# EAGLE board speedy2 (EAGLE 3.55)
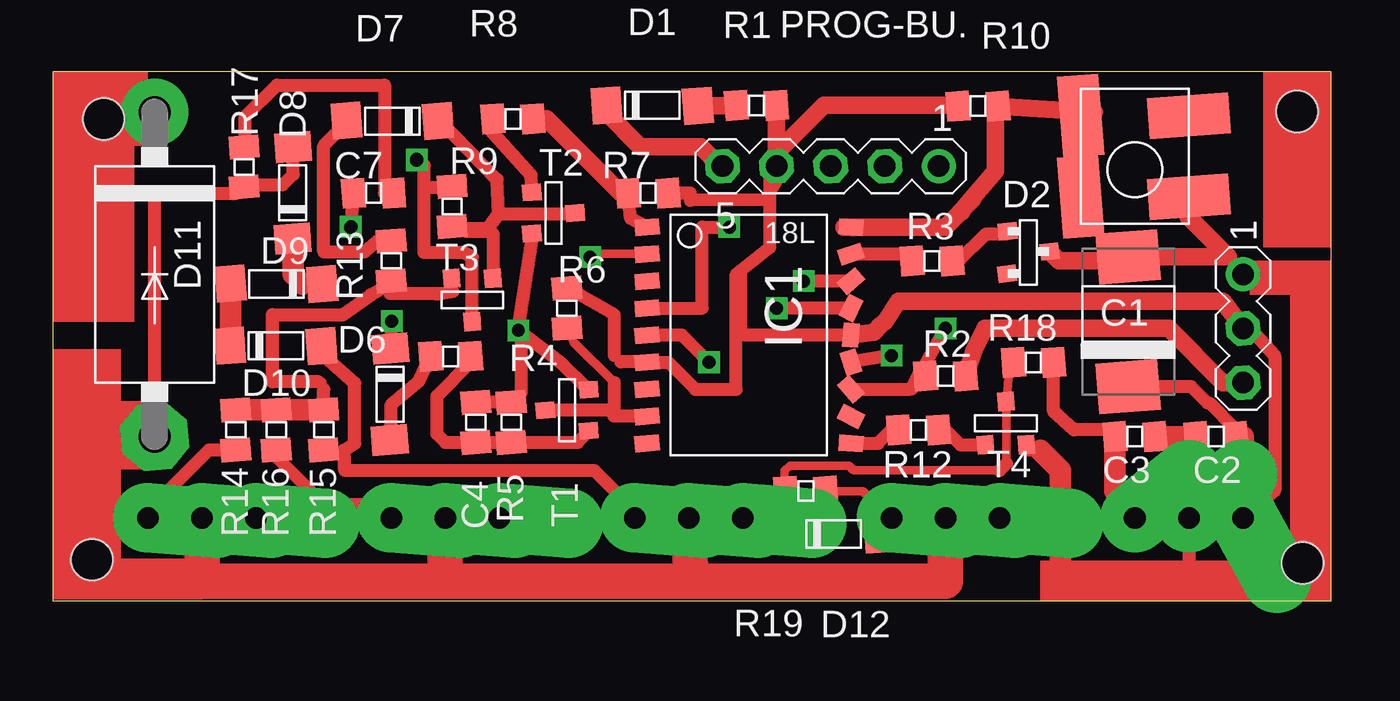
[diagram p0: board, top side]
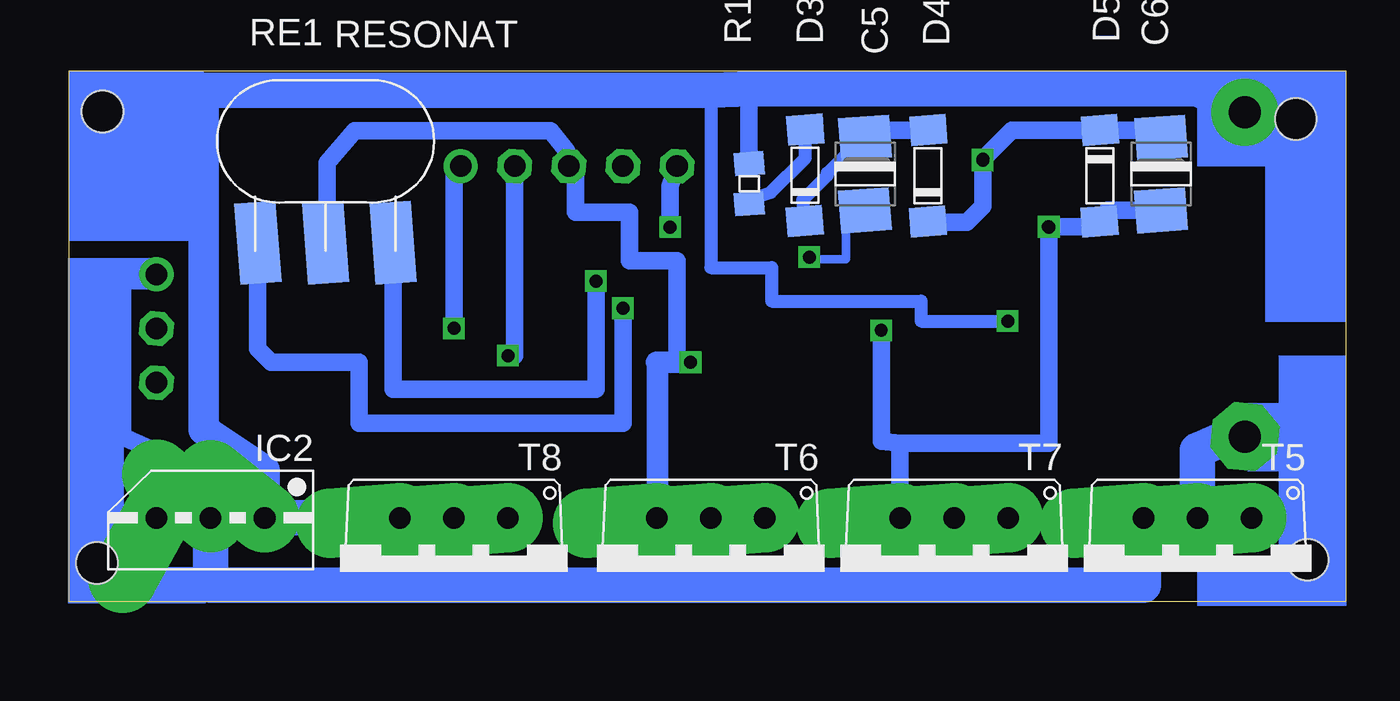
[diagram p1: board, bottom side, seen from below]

Size 60.01 x 24.88 mm. Coordinates in mm from the lower left corner, seen from the top.
Outline: 0,24.88 60.01,24.88 60.01,0 0,0 0,24.88
Copper layers used: Top, Bottom
Holes 1.93 mm at 2.37,22.66 1.82,1.96 58.67,1.81 58.42,23.01

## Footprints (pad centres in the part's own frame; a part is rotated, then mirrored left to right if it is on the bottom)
43 = smd 2.388 x 2.896 rotated 4.4:  3.048,0 | smd 2.388 x 2.896 rotated 4.3:  -3.048,0
05 = smd 1.092 x 1.397 rotated 4.4:  0.94,0 | smd 1.092 x 1.397 rotated 4.3:  -0.94,0
28 = smd 2.007 x 2.388 rotated 4.4:  1.702,0 | smd 2.007 x 2.388 rotated 4.3:  -1.702,0
D-80 = smd 1.397 x 1.702 rotated 4.4:  -2.388,0 | smd 1.397 x 1.702 rotated 4.3:  1.905,-0.025
T-23 = smd 0.787 x 0.889 rotated 6.7:  -1.24,-0.669 | smd 0.787 x 0.889 rotated 5.7:  0.754,-0.688 | smd 0.787 x 0.889 rotated 6.6:  -0.197,-2.662
201-15 = drill 1.499 pad 3.15 round:  -7.62,0 | drill 1.499 pad 3.15 octagon:  7.62,0
03-1 = drill 1.016 pad 1.6 round:  -2.54,0 | drill 1.016 pad 1.6 octagon:  0,0;  2.54,0
-18L = smd 0.762 x 1.143 rotated 4.3:  -5.08,-5.131;  5.08,4.445 | smd 0.762 x 1.143 rotated 4.4:  -3.81,-5.131 | smd 0.762 x 1.143 rotated 4.5:  -2.54,-5.131 | smd 0.762 x 1.143 rotated 4.6:  -1.27,-5.131 | smd 0.762 x 1.143 rotated 4.7:  0,-5.131;  1.27,-5.131 | smd 0.762 x 1.143 rotated 4.8:  2.54,-5.131 | smd 0.762 x 1.143 rotated 4.9:  3.81,-5.131 | smd 0.762 x 1.143 rotated 5:  5.08,-5.131 | smd 0.762 x 1.143 rotated 26.8:  3.81,4.445 | smd 0.762 x 1.143 rotated 49.3:  2.54,4.445 | smd 0.762 x 1.143 rotated 71.8:  1.27,4.445 | smd 0.762 x 1.143 rotated 94.3:  0,4.445 | smd 0.762 x 1.143 rotated 116.8:  -1.27,4.445 | smd 0.762 x 1.143 rotated 139.3:  -2.54,4.445 | smd 0.762 x 1.143 rotated 161.8:  -3.81,4.445 | smd 0.762 x 1.143 rotated 184.3:  -5.08,4.445
MXXS = drill 1.016 pad 3.251 offset:  -2.54,-2.54;  0,-2.54;  2.54,-2.54
05-1 = drill 1.016 pad 1.6 round:  -5.08,0 | drill 1.016 pad 1.6 octagon:  -2.54,0;  0,0;  2.54,0;  5.08,0
SONAT = smd 1.93 x 3.81 rotated 4.5:  3.175,-4.445 | smd 1.93 x 3.81 rotated 4.3:  -3.175,-4.445 | smd 1.93 x 3.81 rotated 4.4:  0,-4.445
T-23' = smd 0.787 x 0.889 rotated 4.4:  0.991,1.016 | smd 0.787 x 0.889 rotated 4.3:  -0.94,1.016 | smd 0.787 x 0.889 rotated 4.5:  0.025,-1.016
220V = drill 1.016 pad 3.251 offset:  -2.54,-2.54;  0,-2.54;  2.54,-2.54
D-SWIT = smd 3.81 x 1.93 rotated 4.3:  -2.54,1.27 | smd 3.81 x 1.93 rotated 4.4:  -2.54,-2.54 | smd 3.81 x 1.93 rotated 274.3:  2.54,1.27 | smd 3.81 x 1.93 rotated 274.4:  2.54,-2.54

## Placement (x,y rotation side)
C1  47u/10  [43]  50.48,13.13 90 top
C2  100n  [05]  54.61,7.74 0 top
C3  100n  [05]  50.8,7.74 180 top
C4  47n  [05]  19.85,8.41 90 top
C5  3u3/20  [28]  22.6,20.07 270 bottom
C6  3u3/20  [28]  8.7,20.07 270 bottom
C7  22n  [05]  15.04,19.17 0 top
D1  Smd-Standard  [D-80]  28.37,23.29 0 top
D2  LED-SMD  [T-23]  44.13,16.63 90 top
D3  LL4148  [D-80]  25.43,20.25 90 bottom
D4  LL4148  [D-80]  19.65,20.23 90 bottom
D5  ZDIO-18V  [D-80]  11.57,19.75 270 bottom
D6  ZDIO-5V1  [D-80]  15.83,9.49 270 top
D7  LL4148  [D-80]  15.68,22.55 180 top
D8  LL4148  [D-80]  11.24,19.43 90 top
D9  ZDIO-22V  [D-80]  10.25,14.91 180 top
D10  ZDIO-22V  [D-80]  10.7,12.02 0 top
D11  SB550  [201-15]  4.76,15.36 270 top
D12  LL4148  [D-80]  36.9,3.17 0 top
EMPF  MA03-1  [03-1]  55.88,12.82 270 top
IC1  16F84SO  [-18L]  33.02,12.5 270 top
IC2  LM2940CT  [MXXS]  53.34,1.39 180 bottom
PROG-BU.  MA05-1  [05-1]  36.51,20.44 180 top
R1  1k  [05]  33.02,23.3 180 top
R2  1k  [05]  41.91,10.59 180 top
R3  470  [05]  41.27,15.99 180 top
R4  1k  [05]  18.67,11.51 180 top
R5  2k2  [05]  21.5,8.41 270 top
R6  47k  [05]  24.13,13.77 90 top
R7  1k  [05]  27.94,19.17 0 top
R8  4k7  [05]  21.59,22.66 0 top
R9  47k  [05]  18.73,18.55 90 top
R10  1k  [05]  43.43,23.26 0 top
R11  47  [05]  28.04,19.62 90 bottom
R12  47k  [05]  40.64,8.05 0 top
R13  470  [05]  15.88,15.99 270 top
R14  220  [05]  8.57,8.05 90 top
R15  220  [05]  12.7,8.05 90 top
R16  220  [05]  10.48,8.05 90 top
R17  47  [05]  8.97,20.4 270 top
R18  10k  [05]  46.04,11.23 0 top
R19  82k  [05]  35.35,5.18 0 top
RE1  RESONAT  [SONAT]  47.94,21.29 0 bottom
T1  BC817  [T-23']  24.13,9.01 270 top
T2  BC817  [T-23']  23.49,18.21 90 top
T3  BC817  [T-23']  19.65,14.15 0 top
T4  BC817  [T-23']  44.77,8.37 180 top
T5  IRF3205  [220V]  6.98,1.39 180 bottom
T6  IRF3205  [220V]  29.84,1.39 180 bottom
T7  IRF3205  [220V]  18.41,1.39 180 bottom
T8  IRF9540 o..  [220V]  41.91,1.39 180 bottom
U$1  SMD-SWIT  [D-SWIT]  50.79,20.27 180 top

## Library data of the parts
C1 C5 C6 D1 D3-D10 D12 R11 R14 R19 = SMD
C2-C4 C7 R2 R15-R17 = DEMO
D2 RE1 U$1 = hans
D11 = DIODE
EMPF PROG-BU. = CON-LSTB
IC1 = PIC
IC2 = V-REG
R1 R3-R10 R12 R13 R18 = DISCRETE
T1-T4 = NPN
T5-T8 = FET

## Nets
+12V: C3. D6. D11. IC2. R11. R18. T8.
GND: C1. C2. C3. C4. C6. C7. D2. D5. EMPF. IC1. IC2. PROG-BU.. R5. RE1. T1. T2. T4. T5. T6. T7. U$1.
N$1: IC1. RE1.
N$3: IC1. PROG-BU..
N$4: C5. IC1.
N$5: D12. R19. T8.
N$6: IC1. R3.
N$8: D6. R4.
N$9: D2. R3.
N$10: R8. T2.
N$11: C4. R4. R5. T1.
N$12: IC1. R6. T1.
N$13: IC1. R7. R8.
N$14: R13. R14. R15. R16. T3.
N$15: R12. T4.
N$16: IC1. R12.
N$17: D12. R18. R19. T4.
N$18: D7. R9. T2. T3.
N$19: IC1. R10. U$1.
N$20: D8. D11. R17. T5. T6. T7. T8.
N$21: D7. R13.
N$22: IC1. RE1.
N$23: EMPF. R2.
N$24: D10. R15. T6.
N$26: D1. IC1. PROG-BU..
N$28: D8. D9.
N$29: IC1. PROG-BU.. R2.
N$30: C5. D3. D4.
N$32: R16. T7.
N$33: D3. R11.
N$34: D1. R1.
N$35: D9. D10.
N$36: C6. D4. D5. R9. T3.
N$37: C7. R17.
N$38: R14. T5.
VCC: C1. C2. EMPF. IC1. IC2. PROG-BU.. R1. R6. R7. R10.

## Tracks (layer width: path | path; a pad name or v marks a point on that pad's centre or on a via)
+12V  (via drill 0.61 pad 1.02)
  Top 0.406: 49.86,7.74 49.85,7.74 | 49.85,7.74 49.85,8.06 | 50.8,3.93 51.12,3.93 | 49.85,7.74 49.53,8.06
  Top 0.61: 51.12,3.93 49.86,5.18 | 46.98,11.23 46.97,8.93 47.94,8.06 49.53,8.06 | v15.9,13.17 15.87,13.17 15.87,11.88 15.83,11.88
  Top 1.016: 49.86,5.18 49.86,7.74
  Bottom 0.406: 50.8,6.15 50.8,6.47 | 50.8,3.93 50.8,3.61 | 27.94,24.06 28.02,24.06 28.04,24.04
  Bottom 0.61: v15.9,13.17 19.97,13.17 19.97,14.1 26.99,14.1 26.99,15.67 29.84,15.67 29.84,24.01
  Bottom 0.813: 28.04,24.04 28.04,20.56
  Bottom 1.422: 53.66,24.01 53.66,8.06 50.8,6.15 50.8,3.93
  Bottom 1.676: 4.76,22.98 6.98,24.06 27.94,24.06 29.84,24.01 53.66,24.01 56.83,23.98 | 50.8,3.93 T8.
GND  (via drill 0.61 pad 1.02)
  Top 0.406: 55.88,15.36 55.56,15.67 55.7,15.67 | v13.97,17.58 v13.98,17.59 | 25.15,9.95 25.09,9.95 25.08,9.96 24.77,10.28 | 22.54,17.26 22.53,17.28 22.48,17.28 | 50.48,16.18 50.48,15.99 50.16,16.31 | 45.72,7.1 45.71,7.12 45.71,7.36 | 27.81,12.53 27.84,12.53 27.87,12.56 27.93,12.5 | 53.34,7.74 53.44,7.74 53.47,7.71 53.5,7.74 C2. | 21.97,9.76 21.52,9.31 | 21.52,9.31 21.42,9.21 21.52,9.21 21.52,9.31 | 19.85,9.35 19.85,9.44 19.87,9.46 19.98,9.35 | v21.84,12.73 21.95,12.73 21.97,12.71 | 21.52,9.31 21.52,9.35 R5. | 55.7,15.67 55.92,15.46 | 55.7,15.67 55.19,16.18 | D2. 46.82,16.46 46.82,16.41
  Top 0.61: 47.31,1.07 53.02,1.07 53.34,1.39 53.34,3.93 | v30.8,11.23 29.53,12.5 27.93,12.5 | v13.98,17.59 C7. | 46.36,7.1 45.72,7.1 | 25.08,9.96 23.81,11.23 v21.84,12.73 22.54,17.26 | 21.97,12.71 21.97,9.76 | R5. 19.98,9.35
  Top 0.813: 50.48,16.18 55.19,16.18 53.29,18.09 53.29,18.96 53.33,19 | 50.48,15.99 47.23,15.99 46.82,16.41
  Top 1.016: 53.34,3.93 53.34,7.74 C3. | 47.31,1.07 47.31,6.15 46.36,7.1
  Bottom 0.406: T7. 20.95,2.34 20.64,0.75 20.95,1.07 | 32.38,3.61 T6. | 53.02,4.24 53.34,3.93 53.66,3.93 53.66,4.56 | 32.38,5.2 32.07,5.2 | 55.56,15.19 55.88,15.36 | 36.51,20.44 36.51,20.12 36.2,20.12 | v30.8,11.23 31.43,11.23 | v13.98,17.59 v13.97,17.58 13.96,17.57 | 11.83,17.59 11.59,17.83 D5. 11.61,17.84 11.67,17.91 11.21,18.37 | 36.62,20.36 36.62,21.16 | 47.87,16.36 47.97,16.26 47.97,16.16
  Bottom 0.813: v13.97,17.58 13.97,7.42 20.95,7.42 | T7. 20.95,7.42 | 53.66,4.56 54.61,6.47 57.47,7.74 57.47,15.14 55.56,15.19 | v21.84,12.73 21.84,7.52 20.95,7.42 | 36.2,20.12 36.2,18.28 33.66,18.28 33.66,15.99 31.43,15.99 31.43,11.23 | v13.98,17.59 11.83,17.59 | 36.62,21.16 37.37,22.11 46.57,22.11 47.87,20.61 47.87,16.36 | 11.21,18.37 8.7,18.37
  Bottom 1.016: 32.35,11.23 v30.8,11.23 | 32.35,11.23 32.38,11.23 | 32.35,11.23 32.35,3.8 32.36,3.8 | T6. 32.38,3.9 32.36,3.9 32.36,3.8 | T6. | 32.38,5.2 T6. | 32.36,3.8 32.36,3.77 | 36.45,20.44 36.45,20.5 | 36.51,20.44 36.45,20.44 | 36.62,20.36 36.45,20.36 36.45,20.44 | 47.87,16.36 47.94,16.36 RE1.
  Bottom 1.676: 32.38,0.75 20.64,0.75 9.52,0.75 T5. | 32.38,0.75 32.38,3.61 | 32.38,0.75 53.34,0.75 53.34,3.93 | 20.95,1.07 T7.
N$1  (via drill 0.61 pad 1.02)
  Top 0.406: v33.97,13.77 34,13.8
  Top 0.61: 34,13.8 37.39,13.8
  Bottom 0.61: 51.22,16.84 51.11,16.84 51.12,16.84 | 51.22,11.87 51.12,11.87
  Bottom 0.813: v33.97,13.77 33.97,8.37 46.36,8.37 46.36,11.23 50.48,11.23 51.12,11.87 | 51.12,11.87 51.12,16.84
N$3  (via drill 0.61 pad 1.02)
  Top 0.406: 39.39,11.57 v39.37,11.55
  Top 0.61: 37.39,11.26 39.39,11.57
  Bottom 0.406: v39.37,11.55 39.05,11.55
  Bottom 0.813: 39.05,11.55 39.05,20.44
N$4  (via drill 0.61 pad 1.02)
  Top 0.406: 27.81,16.34 27.8,16.32 25.37,16.32 v25.22,16.17
  Bottom 0.406: 22.6,18.37 23.49,18.37 23.49,16.08 25.22,16.08 v25.22,16.17
N$5
  Top 0.406: 39.29,3.91 39.31,3.93 39.37,3.93 | 36.29,5.18 38.02,5.18 39.29,3.91 | 38.77,3.14 38.77,3.12 | 38.77,3.14 D12. | 39.29,3.91 38.77,3.91 38.77,3.14
N$6
  Top 0.406: 40.34,15.99 40.32,15.99 40.32,16.34
  Top 0.61: 37.39,16.34 40.32,16.34
N$8
  Top 0.61: 17.73,11.51 17.17,10.36 15.87,9.26 15.87,7.61 15.84,7.58 D6.
N$9
  Top 0.406: R3. 42.55,15.99 | 44.77,17.26 44.82,17.32 44.82,17.38
  Top 0.61: 42.55,15.99 43.81,17.26 44.77,17.26
N$10
  Top 0.406: 20.5,22.16 R8.
  Top 0.61: 22.48,19.21 22.45,20 20.5,22.16
N$11
  Top 0.406: 25.12,8.02 25.15,8.02 | 25.12,8.02 25.07,8.07 | 21.5,7.47 21.51,7.47 21.57,7.41 | 25.17,8.01 25.16,8.02 25.12,8.02 | 19.61,11.25 R4. | C4. 19.85,7.44 19.82,7.41 19.77,7.46
  Top 0.61: C4. 21.5,7.47 24.63,7.47 25.17,8.01 | 19.61,11.25 18.02,9.66 18.02,7.86 18.42,7.46 19.77,7.46
N$12
  Top 0.406: 26.33,8.72 26.03,9.01 23.18,9.01 23.15,8.98 T1. | R6. 24.45,12.18 26.35,10.28
  Top 0.61: 26.33,8.72 27.81,8.72 | 26.35,10.28 26.35,9.01 23.18,9.01
N$13
  Top 0.406: 27.94,17.58 27.94,17.61 27.81,17.61 | R7. 26.99,19.17 26.67,19.17 | 23.18,22.66 22.53,22.66
  Top 0.61: 27.81,17.61 27.11,17.99 26.99,19.17
  Top 0.813: 26.67,19.17 23.18,22.66
N$14
  Top 0.406: 8.57,8.99 8.57,9.01 8.58,8.99 | 10.48,8.99 10.48,9.01 10.49,8.99 | 12.7,9.96 12.63,10.33 12.43,10.33 | 15.49,14.72 15.49,15.04 | 18.77,14.56 18.71,15.17 | 18.26,14.47 17.96,14.44 | 15.88,15.05 15.88,15.04 15.81,14.98 15.81,14.47
  Top 0.61: 12.7,8.99 12.7,9.96 | 12.43,10.33 10.3,10.31 10.3,13.47 13.59,13.45 14.92,14.41 15.49,14.72 | 15.49,15.04 15.81,14.47 18.26,14.47 | 17.96,14.44 18.77,14.56
  Top 1.016: 8.58,8.99 10.48,8.99 | 10.49,8.99 12.7,8.99
N$15
  Top 0.406: 41.58,8.06 41.91,8.06
  Top 0.61: 43.78,7.36 42.61,7.36 41.91,8.06
N$16
  Top 0.406: 37.15,7.42 37.17,7.45 37.39,7.45 37.44,7.45 37.46,7.42 | 39.37,8.06 R12.
  Top 0.61: 39.37,8.06 38.73,7.42 37.46,7.42
N$17
  Top 0.406: 44.45,6.15 40.64,6.15 37.59,6.15 37.36,6.38 34.59,6.38 34.34,6.13 34.34,5.21 34.38,5.17 34.39,5.18 R19. 34.43,5.18 34.43,3.17 | 44.77,6.47 44.77,9.32 44.74,9.35 T4. 44.82,9.88 44.85,10.49 R18. | 34.43,3.17 34.43,3.16 | 34.51,3.17 34.43,3.17
  Top 0.61: 44.45,6.15 44.77,6.47
N$18
  Top 0.406: 20.5,17.61 R9. 19.37,17.26 20.66,17.27 | 24.55,18.21 24.74,18.24 T2. | 20.66,15.31 20.54,15.14 20.64,15.17 | 18.17,22.56 18.07,22.56 | 20.85,19.8 20.82,19.8
  Top 0.61: 20.5,17.61 20.91,18.21 | 20.91,18.21 24.55,18.21 | 20.66,17.27 20.66,15.31 | 20.91,18.21 20.85,19.8 | 20.82,19.8 18.17,22.56
N$19
  Top 0.406: 37.15,17.58 37.17,17.61 37.39,17.61 | 48.89,22.98 U$1. | 44.25,23.14 44.37,23.26 | 43.18,18.85 43.24,18.91 42.81,18.14 42.81,18.53
  Top 0.813: 43.18,18.85 41.91,17.58 37.15,17.58 | 44.37,23.26 48.89,22.98 | 44.25,23.14 44.25,20.21 42.81,18.53
N$20
  Top 0.406: 29.95,0.95 29.84,1.07 | 18.41,0.95 18.41,1.07 | 8.97,19.5 9.02,19.56 9.02,19.46 | 8.97,19.5 8.97,19.46 | 8.97,19.5 8.63,19.17 8.66,19.17 8.67,19.16 | 9.02,19.46 8.97,19.41 | 9.02,19.46 9.12,19.56
  Top 0.61: D11. 4.76,19.17 8.66,19.17 | D8. 11.27,20.06 10.77,19.56 9.12,19.56
  Top 1.676: 41.91,3.93 41.91,0.95 29.95,0.95 | 18.41,0.95 29.95,0.95 | 29.95,0.95 29.84,3.93 | 6.98,3.93 6.98,0.95 18.41,0.95 | 18.41,0.95 18.41,3.93
  Bottom 0.406: 6.98,3.93 7.3,3.61 | 4.76,8.06 D11.
  Bottom 1.676: 6.98,3.93 6.98,7.1 4.76,8.06
N$21
  Top 0.406: 15.56,17.26 15.24,16.95 R13. | 13.82,22.51 13.78,22.55 D7.
  Top 0.61: 15.24,16.95 14.6,16.41 12.7,16.41 12.7,21.39 13.82,22.51
N$22  (via drill 0.61 pad 1.02)
  Top 0.406: v35.24,15.04 35.27,15.07
  Top 0.61: 35.27,15.07 37.39,15.07
  Bottom 0.61: 44.77,16.84
  Bottom 0.813: v35.24,15.04 35.24,9.96 44.77,9.96 44.77,16.84
N$23
  Top 0.813: R2. 43.24,11.77 43.76,12.82 52.39,12.82 54.93,10.28 EMPF.
N$24
  Top 0.406: 27.62,3.93 27.3,3.93 | R15. 13.65,6.78 13.65,7.1
  Top 0.61: R15. 13.68,6.8 13.69,6.15 25.4,6.15 27.62,3.93 | 13.65,7.1 14.16,7.42 14.16,10.26 12.52,11.71 12.6,11.79 D10.
N$26  (via drill 0.61 pad 1.02)
  Top 0.406: 31.42,20.36 31.43,20.37 PROG-BU.. | 27.81,13.8 27.88,13.8 27.92,13.76 27.93,13.77 | 25.98,22.94 25.98,23.29
  Top 0.61: v31.75,17.58 30.48,17.58 30.48,13.77 27.93,13.77
  Top 0.813: 25.98,22.94 27.57,21.36 30.42,21.36 31.42,20.36
  Bottom 0.406: PROG-BU.. 31.75,20.44
  Bottom 0.813: v31.75,17.58 31.75,19.49 PROG-BU..
N$28
  Top 0.406: 11.27,16.91 11.24,16.94 11.24,17.04
  Top 0.61: 12.63,14.91 11.72,14.91
  Top 1.016: 11.72,14.91 11.27,15.36 11.27,16.91
N$29  (via drill 0.61 pad 1.02)
  Top 0.406: 40.32,9.98 37.46,9.96 37.42,9.96 37.39,9.99 | 40.97,10.6 40.65,10.93 40.19,9.96
  Top 0.61: 40.32,9.98 v41.91,12.82 | 37.46,9.96 40.19,9.96
  Bottom 0.406: 41.91,20.12 41.59,20.44
  Bottom 0.813: v41.91,12.82 41.91,20.12
N$30
  Bottom 0.406: 22.61,21.97 22.62,21.96 | 22.61,21.97 C5. 22.55,21.92 | 22.61,21.97 22.44,22.13 22.54,22.13 22.57,22.11 | 25.43,17.86 25.46,17.86 25.47,17.86 25.52,17.91 25.57,17.86 | 24.37,20.11 24.37,20.01
  Bottom 0.61: 22.55,21.92 24.37,20.11 | 24.37,20.01 25.52,18.86 25.52,17.91
  Bottom 0.813: D4. 22.54,22.13
N$32
  Top 0.406: 15.24,4.56 15.88,3.93 | R16. 10.48,6.78
  Top 0.61: 10.48,6.78 12.7,4.56 15.24,4.56
N$33
  Bottom 0.406: 28.07,18.76 28.04,18.73 R11.
  Bottom 0.61: D3. 25.41,20.82 27.02,19.21 27.82,18.96 28.07,18.76
N$34
  Top 0.406: 32.08,23.3 32.02,23.3 32.02,23.27 32.02,23.26
  Top 0.813: D1. 32.02,23.27
N$35
  Top 0.406: 8.41,12.02 8.42,12.01 | 8.31,12.02 8.41,12.02 | 8.41,12.02 8.34,12.09
  Top 1.016: 8.34,12.09 D9.
N$36  (via drill 0.61 pad 1.02)
  Top 0.406: 18.73,19.49 18.73,19.17 18.66,19.45 | 17.42,20.46 17.12,20.76 v17.07,20.76 17.09,20.76 17.09,20.71 v17.07,20.71 | 17.42,19.36 17.41,19.37 17.41,19.45
  Top 0.61: T3. 19.68,16.18 19.28,16.38 17.41,16.38 17.41,19.45 18.66,19.45 | 17.42,19.36 17.42,20.46
  Bottom 0.406: C6. 8.81,21.92 8.82,21.91 9.05,22.14 | 19.67,17.76 19.62,17.81 19.67,17.81 19.67,17.84 19.65,17.84 | 11.57,22.14 11.65,22.14 11.72,22.21
  Bottom 0.813: 11.57,22.14 15.69,22.14 v17.07,20.76 | v17.07,20.71 17.07,18.56 17.82,17.81 19.62,17.81 | 11.65,22.14 9.05,22.14
N$37
  Top 0.406: 15.56,19.17 15.98,19.17 | R17. 9.05,21.34 9.07,21.36 9.02,21.41
  Top 0.61: 15.56,19.17 15.56,24.25 10.51,24.25 9.02,22.76 9.02,21.41
N$38
  Top 0.406: 4.45,3.93 4.45,4.24
  Top 0.61: R14. 7.31,7.12 4.45,4.24
VCC
  Top 0.406: 55.88,7.74 55.55,7.74 55.55,8.07 | 33.97,20.44 33.97,21.07 | 33.97,20.44 34.29,20.12 33.57,18.87 | 33.97,20.44 33.96,20.45 | 55.88,12.82 56.2,12.82 | 26.64,11.26 26.35,11.55 | 24.13,14.72 24.13,14.71 | 33.66,20.12 33.97,20.44 | 33.97,20.44 33.97,20.12 | 33.66,16.63 32.38,15.67 32.38,12.82 32.41,12.53 | 38.85,12.97 39.05,13.13 | 41.98,23.31 R10. | 27.81,11.26 27.87,11.26 27.9,11.23 | 37.39,12.53 37.4,12.53 37.43,12.5 | 54.22,9.31 54.24,9.32 54.29,9.32
  Top 0.61: 33.57,18.87 29.92,18.84 29.92,19.17 28.88,19.17 | 56.2,12.82 57.37,11.55 57.37,5.2 IC2. | 55.55,8.07 54.29,9.32 | 27.81,11.26 26.64,11.26 | 26.35,11.55 26.35,13.45 24.13,14.72 | 33.66,20.12 33.66,16.63 32.07,15.36 32.07,9.96 30.16,9.96 28.89,11.23 27.9,11.23 | 32.41,12.53 37.39,12.53 | C1. 53.44,10.09 54.22,9.31
  Top 0.813: 33.96,20.45 R1. | 33.97,21.07 36.2,23.3 40.43,23.3 41.98,23.31 | 38.85,12.97 38.53,12.65 37.43,12.5 | 39.05,13.13 39.69,14.09 54.93,14.09 55.88,12.82
  Top 1.016: IC2. 55.88,7.74
(copper drawn outside any net)
  shapes: Bottom area x9, Top area x11

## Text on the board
Document: Motor+ | Akku+ | Motor- | Akku-
tDocu: Setup | Gnd | +5V | Sig.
